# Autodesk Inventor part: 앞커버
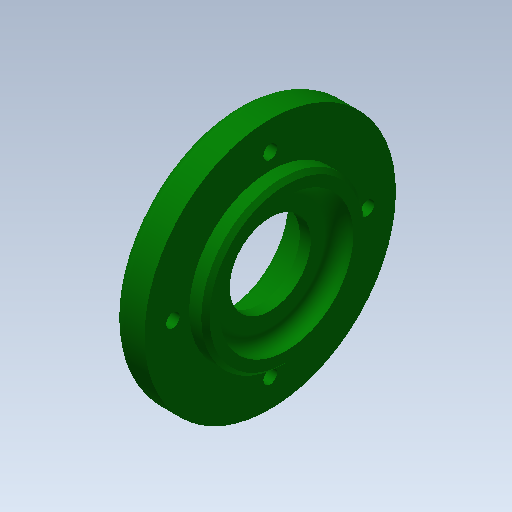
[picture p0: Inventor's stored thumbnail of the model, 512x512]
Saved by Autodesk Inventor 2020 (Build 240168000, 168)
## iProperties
Created: 2015-09
Part Number: 앞커버
Material: 알루미늄 6061
Document SubType Name: Modeling
Designer: mduedu
Density: 2.71 g/cm^3
Mass: 58.9874 g
Surface Area: 98.7754 cm^2
Volume: 21.7666 cm^3
Appearance: 진녹색
Author: mduedu
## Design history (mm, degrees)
sketch "스케치1"
  geometry: L1 (-8, 67)-(-12, 67); L2 (-12, 67)-(-12, 78); L3 (-12, 78)-(-20, 78); L4 (-20, 78)-(-20, 66); L5 (-23, 66)-(-23, 57); L6 (-23, 57)-(-8, 57); L7 (-8, 57)-(-8, 67); L8 (-79.5, 39.5)-(-79.5, 54.5) reference; L9 (48.5, 54.5)-(48.5, 39.5) reference; L10 (-79.5, 47)-(48.5, 47); L11 (-20, 66)-(-23, 66); 3 further points
  constraints: 18 end point, 6 parallel, 4 midpoint, 1 horizontal, 1 perpendicular, 1 vertical alignment
  dimensions: "d0" = 15 distance between parallel lines of L7 L5; "d2" = 20 diameter of L6 L10; "d3" = 40 diameter of L1 L10; "d5" = 4 distance of L1.start L1.end; "d6" = 62 diameter of L3 L10; "d7" = 8 distance of L2.end L3.end; "d8" = 38 diameter of L4.end L10
revolve "회전1" sketch "스케치1" stored, may be unused: angle "d4" = 90 deg
sketch "스케치2"
  geometry: C1 r 31 at (0, 0) reference; 2 further points
  constraints: 1 coincident
hole "구멍1" sketch "스케치2" at (0, 0) diameter "d11" = 33; stored, may be unused: countersink angle "d15" = 90 deg, drill point angle "d17" = 0 deg; dims "d12" = 6, "d13" = 4, "d14" = 2, "d16" = 4
fillet "모깎기1" dims "d18" = 3
fillet "모깎기2" dims "d19" = 1, "d60" = 3
sketch "스케치3"
  geometry: C1 r 31 at (0, 0) reference; 2 further points
  constraints: 1 coincident
hole "구멍2" sketch "스케치3" at (0, 0) diameter "d20" = 30; stored, may be unused: countersink angle "d24" = 90 deg, drill point angle "d26" = 0 deg; dims "d21" = 6, "d22" = 4, "d23" = 2, "d25" = 8.3
fillet "모깎기3" dims "d27" = 0.3
chamfer "모따기1" distance "d28" = 0.8; stored, may be unused: second distance "d29" = 2, angle "d30" = 30 deg
sketch "스케치4" dims "d31" = 56
  geometry: C1 r 31 at (0, 0) reference; 6 further points
  constraints: 2 vertical alignment, 1 coincident, 7 other
  dimensions: "d36" = 360 deg dimension on C1.centre point (0, 28) (derived)
sketch "스케치7"
  geometry: C1 r 30.5 at (0, 0) reference; A1 r 24 centre (0, 0) between (24, 0) and (0, 24); 2 further points
  constraints: 4 point on circle, 2 horizontal alignment, 2 vertical alignment, 1 centre point, 1 coincident
  dimensions: "d58" = 48 diameter of A1
hole "구멍4" sketch "스케치7" at (0, 24), (-24, 0), (24, 0), (0, -24) diameter "d48" = 3.4; stored, may be unused: countersink angle "d52" = 90 deg, drill point angle "d54" = 0 deg; dims "d49" = 6, "d50" = 6.5, "d51" = 3.4, "d53" = 8
chamfer "모따기2" distance "d55" = 1; stored, may be unused: second distance "d56" = 2, angle "d57" = 45 deg
node "솔리드1"
node "참조1"
node "참조2"
node "참조3"
